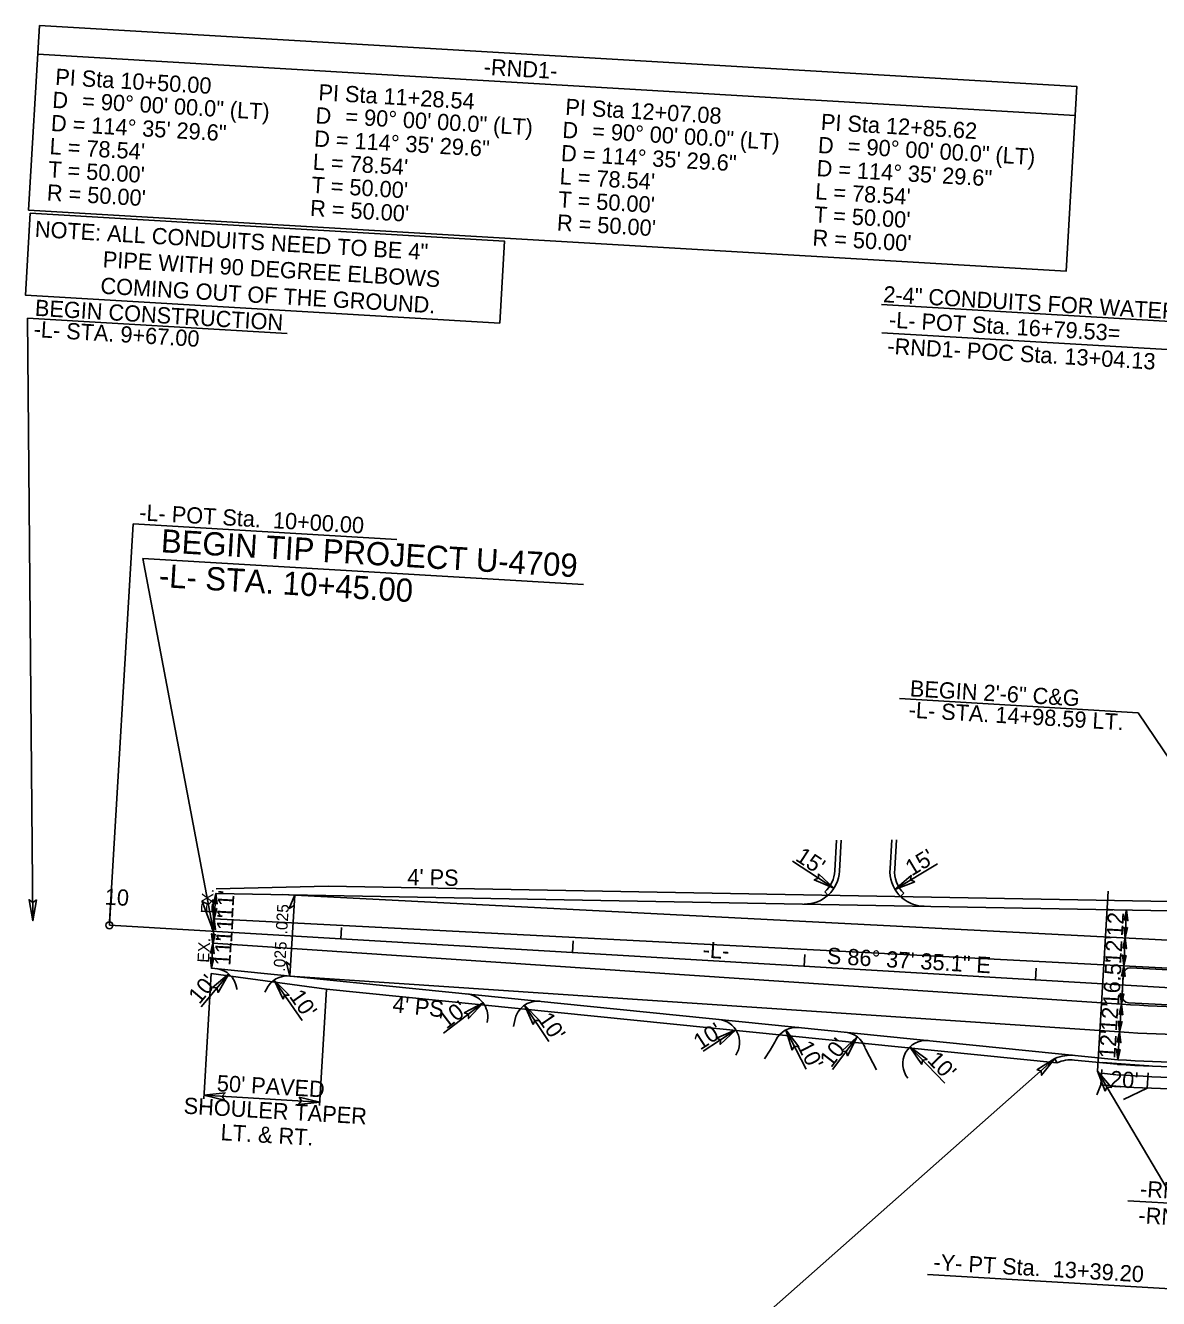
# Model space of a CAD drawing. Extents: x 2010838 to 2015151, y 441905 to 447792.
# Drawn here: x 2011203 to 2011692, y 444872 to 445421 of the extents above; entities that cross this region are included whole.
import ezdxf

# ---------------------------------------------------------------- set-up
doc = ezdxf.new("R2010")
doc.units = 0
for name, color, linetype in [('A-Wall-Blow', 7, 'Continuous'), ('A-Wall-Comp', 7, 'Continuous'), ('B-Border Text', 7, 'Continuous'), ('B-Sheet Number', 7, 'Continuous'), ('C-Building', 7, 'Continuous'), ('C-CURB STOPS', 7, 'Continuous'), ('C-EOP 1', 7, 'Continuous'), ('C-Grave Plots', 7, 'Continuous'), ('CLRD', 7, 'Continuous'), ('Cont-2-Lidar', 7, 'Continuous'), ('Default_10ft_LIDAR_Contou', 7, 'Continuous'), ('Default_2FT_LIDAR_Contour', 7, 'Continuous'), ('Default_Parcels', 7, 'Continuous'), ('HATCH', 7, 'Continuous'), ('s-Existing Major', 7, 'Continuous'), ('S-Existing Minor', 7, 'Continuous'), ('S-overhead electric', 7, 'Continuous'), ('TEXT-LG', 7, 'Continuous'), ('TEXT-MED', 7, 'Continuous'), ('X2', 7, 'Continuous'), ('X3', 7, 'Continuous')]:
    doc.layers.add(name, color=color, linetype=linetype)

msp = doc.modelspace()

# ---------------------------------------------------------------- linework, layer by layer
at = {"layer": 'A-Wall-Blow'}
msp.add_line((2011317.26, 445010.73), (2011319.32, 445045.75), dxfattribs=at)
at = {"layer": 'A-Wall-Comp'}
for points in [[(2011319.32, 445045.75), (2011316.97, 445039.88), (2011319.05, 445041.14)], [(2011317.26, 445010.73), (2011315.61, 445016.84), (2011317.53, 445015.35)]]:
    msp.add_lwpolyline(points, close=True, dxfattribs=at)
at = {"layer": 'B-Border Text'}
for p, q in [((2011285.42, 445048.38), (2011333.76, 445049.49)), ((2011333.76, 445049.49), (2011740.42, 445042.11)), ((2011283.27, 445011.91), (2011332.95, 445005.13)), ((2011332.95, 445005.13), (2011647.87, 444973.31))]:
    msp.add_line(p, q, dxfattribs=at)
at = {"layer": 'B-Sheet Number'}
for p, q in [((2011667.3, 444970.44), (2011666.83, 444963.82)), ((2011687.25, 444969.02), (2011686.78, 444962.46))]:
    msp.add_line(p, q, dxfattribs=at)
at = {"layer": 'C-Building'}
for p, q in [((2011339.24, 445026.75), (2011339.53, 445031.74)), ((2011439.06, 445020.86), (2011439.36, 445025.86)), ((2011538.89, 445014.98), (2011539.19, 445019.97)), ((2011638.72, 445009.09), (2011639.01, 445014.09))]:
    msp.add_line(p, q, dxfattribs=at)
at = {"layer": 'C-CURB STOPS'}
for p, q in [((2011713.24, 445012.56), (2011679.66, 445014.28)), ((2011679.66, 445014.28), (2011729.14, 445011.74)), ((2011676.51, 445011.46), (2011675.98, 445002.35)), ((2011675.98, 445002.35), (2011676.51, 445011.46))]:
    msp.add_line(p, q, dxfattribs=at)
for centre, radius, start, end in [((2011679.51, 445011.29), 3, 87.0578, 176.6264), ((2011679.51, 445011.29), 3, 87.0578, 176.6264), ((2011678.97, 445002.18), 3, 176.6264, 266.4449), ((2011678.97, 445002.18), 3, 176.6264, 266.4449), ((2011714.7, 445577.32), 579.25, 266.1491, 266.16124), ((2011714.7, 445577.32), 579.25, 266.4449, 268.70458)]:
    msp.add_arc(centre, radius, start, end, dxfattribs=at)
at = {"layer": 'C-EOP 1'}
msp.add_line((2011239.41, 445032.63), (2011239.88, 445040.62), dxfattribs=at)
msp.add_line((2011239.41, 445032.63), (2011239.88, 445040.62), dxfattribs=at)
at = {"layer": 'CLRD'}
msp.add_line((2011239.41, 445032.63), (2013147.4, 444920.16), dxfattribs=at)
at = {"layer": 'Default_10ft_LIDAR_Contou'}
for p, q in [((2011572.45, 445288.09), (2011697.89, 445280.7)), ((2011239.5, 445034.13), (2011249.61, 445205.68)), ((2011249.61, 445205.68), (2011363.35, 445198.98)), ((2011678.53, 444913.87), (2011806.71, 444906.31)), ((2011708.02, 444875.19), (2011592.09, 444882.02))]:
    msp.add_line(p, q, dxfattribs=at)
msp.add_circle((2011239.41, 445032.63), 1.5, dxfattribs=at)
msp.add_circle((2011239.41, 445032.63), 1.5, dxfattribs=at)
at = {"layer": 'Default_Parcels'}
msp.add_line((2011208.5, 445408.12), (2011655.8, 445381.75), dxfattribs=at)
msp.add_lwpolyline([(2011209.23, 445420.52), (2011656.54, 445394.15), (2011651.84, 445314.58), (2011204.54, 445340.94)], close=True, dxfattribs=at)
at = {"layer": 'HATCH'}
for p, q in [((2011715.51, 445025.21), (2011313.84, 445045.85)), ((2011674.95, 444986.65), (2011317.21, 445010.73))]:
    msp.add_line(p, q, dxfattribs=at)
msp.add_arc((2011714.7, 445577.32), 592, 266.1491, 278.32461, dxfattribs=at)
at = {"layer": 's-Existing Major'}
for points in [[(2011545.06, 445054.8), (2011551.77, 445048.6), (2011543.31, 445052.18), (2011545.14, 445052.9)], [(2011586.59, 445051.4), (2011578.08, 445048.08), (2011585, 445054.12), (2011584.84, 445052.16)], [(2011284.26, 445041.92), (2011285.3, 445046.37), (2011285.83, 445041.81), (2011285.07, 445042.43)], [(2011207.93, 445043.59), (2011206.47, 445034.57), (2011204.78, 445043.61), (2011206.39, 445042.47)], [(2011284.1, 445043.68), (2011284.33, 445029.98), (2011279.44, 445042.87), (2011282.12, 445041.63)], [(2011283.61, 445030.94), (2011284.65, 445035.39), (2011285.18, 445030.83), (2011284.42, 445031.45)], [(2011285.69, 445039.84), (2011284.65, 445035.39), (2011284.12, 445039.95), (2011284.88, 445039.33)], [(2011676.93, 445034.79), (2011677.96, 445039.24), (2011678.5, 445034.68), (2011677.73, 445035.3)], [(2011678.38, 445031.62), (2011677.34, 445027.17), (2011676.81, 445031.73), (2011677.58, 445031.11)], [(2011283, 445020.55), (2011284.04, 445024.99), (2011284.57, 445020.43), (2011283.81, 445021.05)], [(2011285.04, 445028.86), (2011284, 445024.41), (2011283.47, 445028.97), (2011284.24, 445028.35)], [(2011676.3, 445022.72), (2011677.34, 445027.17), (2011677.88, 445022.61), (2011677.11, 445023.23)], [(2011284.44, 445018.6), (2011283.4, 445014.15), (2011282.87, 445018.72), (2011283.63, 445018.1)], [(2011677.77, 445019.63), (2011676.73, 445015.19), (2011676.2, 445019.75), (2011676.96, 445019.13)], [(2011675.69, 445010.74), (2011676.73, 445015.19), (2011677.26, 445010.62), (2011676.49, 445011.24)], [(2011283.9, 445005.76), (2011290.88, 445011.65), (2011286.27, 445003.69), (2011285.79, 445005.6)], [(2011314.29, 445000.73), (2011310.45, 445009.02), (2011316.91, 445002.48), (2011314.94, 445002.52)], [(2011676.79, 445003.07), (2011675.75, 444998.63), (2011675.22, 445003.19), (2011675.98, 445002.57)], [(2011392.41, 444994.91), (2011400.49, 444999.16), (2011394.28, 444992.38), (2011394.22, 444994.35)], [(2011422.15, 444989.86), (2011418.39, 444998.19), (2011424.79, 444991.58), (2011422.82, 444991.64)], [(2011674.71, 444994.18), (2011675.75, 444998.63), (2011676.28, 444994.06), (2011675.52, 444994.68)], [(2011675.98, 444991.1), (2011674.95, 444986.65), (2011674.41, 444991.22), (2011675.18, 444990.6)], [(2011501.07, 444983.96), (2011509.46, 444987.56), (2011502.75, 444981.29), (2011502.84, 444983.26)], [(2011533.79, 444978.81), (2011531.07, 444987.52), (2011536.61, 444980.2), (2011534.67, 444980.49)], [(2011673.91, 444982.21), (2011674.95, 444986.65), (2011675.48, 444982.09), (2011674.71, 444982.71)], [(2011555.14, 444978.32), (2011561.85, 444984.52), (2011557.61, 444976.37), (2011557.04, 444978.25)], [(2011589.65, 444972.63), (2011584.53, 444980.19), (2011591.96, 444974.78), (2011590.01, 444974.49)], [(2011639.28, 444970.34), (2011647.05, 444975.14), (2011641.32, 444967.95), (2011641.13, 444969.91)], [(2011675.18, 444979.13), (2011674.14, 444974.68), (2011673.61, 444979.24), (2011674.37, 444978.62)], [(2011668.63, 444961.14), (2011665.38, 444969.67), (2011671.36, 444962.7), (2011669.4, 444962.87)], [(2011289.06, 444957.3), (2011280.17, 444959.38), (2011289.3, 444960.44), (2011288.06, 444958.91)], [(2011321.19, 444958.51), (2011330.08, 444956.44), (2011320.96, 444955.37), (2011322.2, 444956.9)]]:
    msp.add_lwpolyline(points, close=True, dxfattribs=at)
at = {"layer": 'S-Existing Minor'}
for p, q in [((2011765.91, 445288.76), (2011572.29, 445300.18)), ((2011206.47, 445034.57), (2011204.04, 445294.29)), ((2011204.04, 445294.29), (2011316.12, 445287.68)), ((2011253.83, 445190.74), (2011443.74, 445179.55)), ((2011284.33, 445029.98), (2011253.83, 445190.74)), ((2011682.87, 445124.26), (2011580.06, 445130.32)), ((2011682.87, 445124.26), (2011739.33, 445040.43)), ((2011551.77, 445048.6), (2011533.84, 445060.23)), ((2011578.08, 445048.08), (2011596.45, 445059.15)), ((2011285.3, 445046.37), (2011284.65, 445035.39)), ((2011284.65, 445035.39), (2011284, 445024.41)), ((2011677.96, 445039.24), (2011677.34, 445027.17)), ((2011284.04, 445024.99), (2011283.39, 445014.01)), ((2011677.34, 445027.17), (2011676.73, 445015.19)), ((2011676.73, 445015.19), (2011675.75, 444998.63)), ((2011290.88, 445011.65), (2011278.93, 444997.46)), ((2011283.27, 445011.91), (2011280.08, 444957.79)), ((2011310.45, 445009.02), (2011322.47, 444991.62)), ((2011330, 444954.98), (2011332.95, 445005.12)), ((2011400.49, 444999.16), (2011383.39, 444986.06)), ((2011418.39, 444998.19), (2011428.93, 444982.58)), ((2011675.75, 444998.63), (2011674.95, 444986.65)), ((2011509.46, 444987.56), (2011495.35, 444978.39)), ((2011531.07, 444987.52), (2011539.74, 444970.58)), ((2011674.95, 444986.65), (2011674.14, 444974.68)), ((2011561.85, 444984.52), (2011551.1, 444970.5)), ((2011647.05, 444975.14), (2011458.89, 444808.88)), ((2011584.53, 444980.19), (2011599.6, 444964.53)), ((2011539.74, 444970.58), (2011539.74, 444970.58)), ((2011915.11, 444547.35), (2011665.38, 444969.67)), ((2011280.17, 444959.38), (2011330.08, 444956.44))]:
    msp.add_line(p, q, dxfattribs=at)
msp.add_lwpolyline([(2011205.31, 445339.55), (2011409.81, 445327.49), (2011407.73, 445292.22), (2011203.23, 445304.28)], close=True, dxfattribs=at)
at = {"layer": 'S-overhead electric'}
for p, q in [((2011554.17, 445055.97), (2011554.87, 445069.28)), ((2011575.98, 445057.05), (2011576.73, 445069.48)), ((2011285.3, 445046.37), (2011747.28, 445037.98)), ((2011713.28, 445013.31), (2011284.65, 445035.34)), ((2011675.75, 444998.63), (2011284.04, 445024.99)), ((2011283.4, 445014.15), (2011674.14, 444974.68)), ((2011402.46, 444991.71), (2011402.33, 444990.76)), ((2011414.14, 444991.6), (2011413.68, 444989.01)), ((2011666.83, 444963.82), (2011665.06, 444959.57)), ((2011686.78, 444962.46), (2011676.64, 444957.58))]:
    msp.add_line(p, q, dxfattribs=at)
for points in [[(2011294.35, 445005.32), (2011294.39, 445005.01)], [(2011306.48, 445003.78), (2011307, 445004.87), (2011307.11, 445005.09)], [(2011521.81, 444975.06), (2011524.21, 444978.73), (2011526.26, 444982.27), (2011526.67, 444983.08)], [(2011565.16, 444980.01), (2011565.49, 444979.12), (2011570.13, 444970.35)]]:
    msp.add_lwpolyline(points, dxfattribs=at)
for centre, radius, start, end in [((2011539.19, 445056.76), 15, 268.9596, 356.9851), ((2011590.93, 445055.82), 15, 175.3022, 268.9596), ((2011284.44, 445004), 10, 7.6226, 84.2226), ((2011316.13, 445000.79), 10, 84.2226, 154.5125), ((2011392.56, 444993.08), 10, 352.2626, 84.2314), ((2011714.7, 445577.32), 580, 266.1491, 278.32461), ((2011423.99, 444989.9), 10, 84.2314, 170.0562), ((2011501.08, 444982.11), 10, 327.1859, 84.2314), ((2011535.62, 444978.62), 10, 84.2314, 153.3011), ((2011555.77, 444976.59), 10, 20.2726, 84.2314), ((2011591.46, 444972.98), 10, 84.2314, 218.9216), ((2011654, 444959.63), 17, 84.2313, 114.1578), ((2011715.1, 445583.3), 610, 266.1491, 277.4453)]:
    msp.add_arc(centre, radius, start, end, dxfattribs=at)
at = {"layer": 'TEXT-LG'}
for p, q in [((2011666.83, 444963.86), (2011672.98, 444963.24)), ((2011667.18, 444968.85), (2011673.48, 444968.21))]:
    msp.add_line(p, q, dxfattribs=at)
for radius in [616.5, 621.5]:
    msp.add_arc((2011715.1, 445583.3), radius, 266.1491, 277.4453, dxfattribs=at)
at = {"layer": 'TEXT-MED'}
for p, q in [((2011552.17, 445056.08), (2011552.86, 445069.26)), ((2011577.97, 445056.93), (2011578.73, 445069.5)), ((2011547.85, 445047.07), (2011549.18, 445045.58)), ((2011581.92, 445046.45), (2011580.53, 445045.01)), ((2011647.87, 444973.31), (2011647.05, 444975.14)), ((2011655.51, 444974.55), (2011673.94, 444972.69))]:
    msp.add_line(p, q, dxfattribs=at)
for centre, radius, start, end in [((2011539.19, 445056.76), 13, 311.793, 356.9851), ((2011590.93, 445055.82), 13, 175.3022, 226.1263), ((2011715.1, 445583.3), 612, 266.1491, 277.4453), ((2011654, 444959.63), 15, 84.2313, 114.1578)]:
    msp.add_arc(centre, radius, start, end, dxfattribs=at)
at = {"layer": 'X2'}
msp.add_line((2011687.46, 444972.01), (2011667.51, 444973.43), dxfattribs=at)
at = {"layer": 'X3'}
msp.add_line((2011665.38, 444969.67), (2011669.96, 445047.35), dxfattribs=at)

# ---------------------------------------------------------------- texts
at = {"layer": 'A-Wall-Blow'}
for s, p in [('EX.', (2011283.78, 445037.58)), ('.025', (2011316.04, 445028.62)), ('EX.', (2011282.32, 445016.39)), ('.025', (2011315.1, 445012.53))]:
    msp.add_text(s, height=5, rotation=86.6264, dxfattribs=at).set_placement(p)
at = {"layer": 'C-Grave Plots'}
for s, height, rotation, p in [('BEGIN CONSTRUCTION', 7, 356.5552, (2011207.16, 445295.4)), ('-L- STA. 9+67.00', 7, 356.5552, (2011206.61, 445286.24)), ('BEGIN TIP PROJECT U-4709', 10, 356.5552, (2011261.45, 445193.45)), ('-L- STA. 10+45.00', 10, 356.5552, (2011260.55, 445178.48)), ("15'", 7, 327.0221, (2011534.73, 445060.84)), ("15'", 7, 31.0678, (2011585.3, 445053.63)), ("4' PS", 7, 358.9596, (2011367.81, 445049.98)), ("11'", 7, 86.6264, (2011292.7, 445035.35)), ("11'", 7, 86.6264, (2011292.29, 445025)), ("12'", 7, 86.6264, (2011676.25, 445027.66)), ("11'", 7, 86.6264, (2011291.55, 445015.05)), ("12'", 7, 86.6264, (2011675.55, 445015.75)), ("16.5'", 7, 86.6264, (2011674.67, 444997.94)), ("10'", 7, 49.897, (2011278.2, 444998.27)), ("10'", 7, 304.6345, (2011316.69, 445001.97)), ("4' PS", 7, 354.2521, (2011361.23, 444995.16)), ("10'", 7, 37.4516, (2011384.74, 444987.66)), ("12'", 7, 86.1491, (2011673.71, 444986.76)), ("10'", 7, 304.0337, (2011423.86, 444992.15)), ("10'", 7, 33.027, (2011494.14, 444978.57)), ("12'", 7, 86.1491, (2011673.02, 444974.97)), ("10'", 7, 297.0971, (2011535.73, 444980.63)), ("10'", 7, 52.5372, (2011550.6, 444970.89)), ("10'", 7, 313.9127, (2011591.62, 444974.17)), ("20'", 7, 356.6264, (2011670.66, 444962.96)), ("50' PAVED", 7, 356.6264, (2011285.58, 444961.13)), ('SHOULER TAPER', 7, 356.6264, (2011271.28, 444951.45)), ('LT. & RT.', 7, 356.6264, (2011287.23, 444939.99))]:
    msp.add_text(s, height=height, rotation=rotation, dxfattribs=at).set_placement(p)
at = {"layer": 'Cont-2-Lidar'}
msp.add_text('S 86%%d 37\' 35.1" E', height=7, rotation=356.6264, dxfattribs=at).set_placement((2011548.56, 445016.07))
at = {"layer": 'Default_10ft_LIDAR_Contou'}
for s, p in [('-L- POT Sta. 16+79.53=', (2011575.33, 445290.3)), ('-RND1- POC Sta. 13+04.13', (2011574.66, 445278.95)), ('-L- POT Sta.  10+00.00', (2011252.12, 445207.22)), ('-RND1- PC Sta.  10+00.00', (2011683.58, 444915.59)), ('-RND1- PC Sta. 13+14.16', (2011682.91, 444904.24)), ('-Y- PT Sta.  13+39.20', (2011594.53, 444884.04))]:
    msp.add_text(s, height=7, rotation=356.6264, dxfattribs=at).set_placement(p)
at = {"layer": 'Default_2FT_LIDAR_Contour'}
for s, p in [('10', (2011237.27, 445041.56)), ('-L-', (2011495.04, 445018.72))]:
    msp.add_text(s, height=7, rotation=356.6264, dxfattribs=at).set_placement(p)
at = {"layer": 'Default_Parcels'}
for s, p in [('-RND1-', (2011400.64, 445399.29)), ('PI Sta 10+50.00', (2011215.92, 445394.97)), ('D', (2011214.66, 445385.03)), ('PI Sta 11+28.54', (2011329.39, 445388.28)), ('= 90%%d 00\' 00.0" (LT)', (2011227.51, 445384.57)), ('PI Sta 12+07.08', (2011435.81, 445382.01)), ('D = 114%%d 35\' 29.6"', (2011214.07, 445375.05)), ('D', (2011328.13, 445378.34)), ('= 90%%d 00\' 00.0" (LT)', (2011340.98, 445377.88)), ('PI Sta 12+85.62', (2011546, 445375.51)), ('D', (2011434.55, 445372.07)), ('= 90%%d 00\' 00.0" (LT)', (2011447.4, 445371.6)), ("L = 78.54'", (2011213.48, 445365.06)), ('D = 114%%d 35\' 29.6"', (2011327.54, 445368.36)), ('D', (2011544.74, 445365.57)), ('= 90%%d 00\' 00.0" (LT)', (2011557.58, 445365.11)), ("L = 78.54'", (2011326.96, 445358.37)), ('D = 114%%d 35\' 29.6"', (2011433.96, 445362.08)), ("T = 50.00'", (2011212.9, 445355.08)), ("L = 78.54'", (2011433.38, 445352.1)), ('D = 114%%d 35\' 29.6"', (2011544.15, 445355.59)), ("T = 50.00'", (2011326.37, 445348.39)), ("R = 50.00'", (2011212.31, 445345.1)), ("T = 50.00'", (2011432.79, 445342.12)), ("L = 78.54'", (2011543.56, 445345.61)), ("R = 50.00'", (2011325.78, 445338.41)), ("T = 50.00'", (2011542.97, 445335.62)), ("R = 50.00'", (2011432.2, 445332.14)), ("R = 50.00'", (2011542.38, 445325.64))]:
    msp.add_text(s, height=7, rotation=356.6264, dxfattribs=at).set_placement(p)
at = {"layer": 'S-Existing Minor'}
for s, p in [('NOTE: ALL CONDUITS NEED TO BE 4" ', (2011207.14, 445329.38)), ('PIPE WITH 90 DEGREE ELBOWS ', (2011236.41, 445316.26)), ('COMING OUT OF THE GROUND.', (2011235.4, 445304.92)), ('2-4" CONDUITS FOR WATER AND POWER', (2011572.9, 445301.23)), ('BEGIN 2\'-6" C&G', (2011584.36, 445131.33)), ('-L- STA. 14+98.59 LT.', (2011583.83, 445122.17))]:
    msp.add_text(s, height=7, rotation=356.6264, dxfattribs=at).set_placement(p)

doc.saveas('drawing.dxf')
